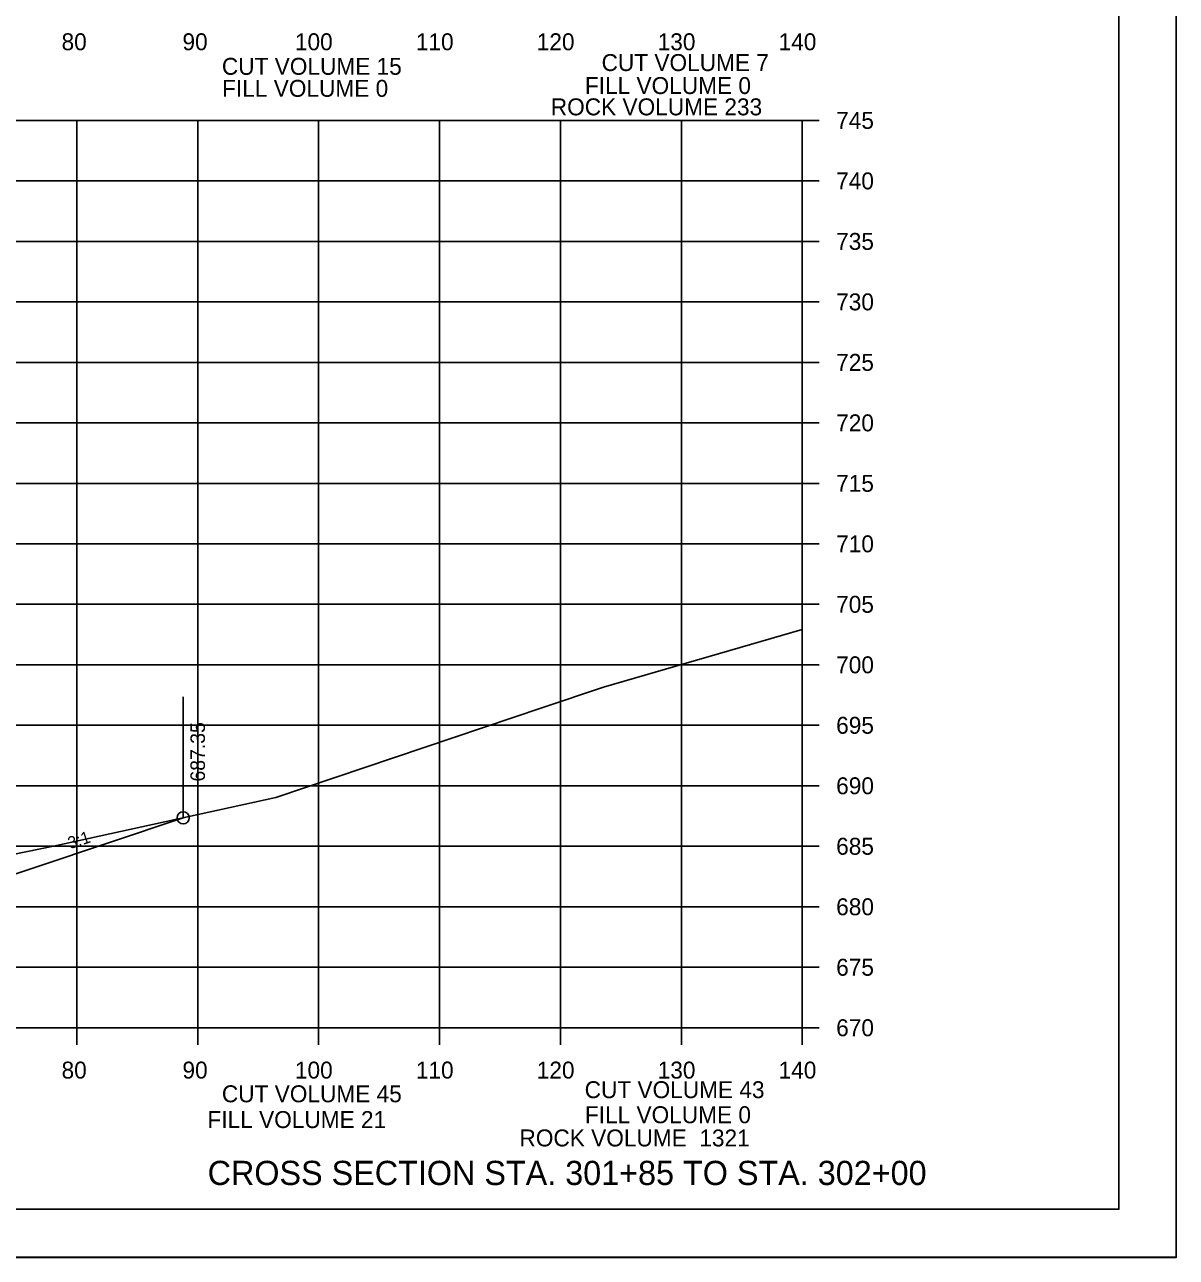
# Model space of a CAD drawing. Extents: x 1370515 to 1370849, y 383299 to 386073.
# Drawn here: x 1370753.5 to 1370848.7, y 383726.1 to 383828 of the extents above; entities that cross this region are included whole.
import ezdxf

# ---------------------------------------------------------------- set-up
doc = ezdxf.new("R2010")
doc.units = 0
for name, color, linetype in [('R_Axis', 7, 'Continuous'), ('R_Axis Annot', 7, 'Continuous'), ('R_Border', 7, 'Continuous'), ('R_Draft', 7, 'Continuous'), ('R_Exist Surface', 7, 'Continuous'), ('R_Fin Surface', 7, 'Continuous'), ('R_Grid', 7, 'Continuous'), ('R_No Plot', 7, 'Continuous'), ('R_Xsect Elev', 7, 'Continuous'), ('R_Xsect Slope', 7, 'Continuous')]:
    doc.layers.add(name, color=color, linetype=linetype)

msp = doc.modelspace()

# ---------------------------------------------------------------- linework, layer by layer
at = {"layer": 'R_Axis'}
for p, q in [((1370819.2, 383820.08), (1370816.4, 383820.08)), ((1370817.8, 383745.08), (1370817.8, 383820.08)), ((1370819.2, 383815.08), (1370816.4, 383815.08)), ((1370819.2, 383810.08), (1370816.4, 383810.08)), ((1370819.2, 383805.08), (1370816.4, 383805.08)), ((1370819.2, 383800.08), (1370816.4, 383800.08)), ((1370819.2, 383795.08), (1370816.4, 383795.08)), ((1370819.2, 383790.08), (1370816.4, 383790.08)), ((1370819.2, 383785.08), (1370816.4, 383785.08)), ((1370819.2, 383780.08), (1370816.4, 383780.08)), ((1370819.2, 383775.08), (1370816.4, 383775.08)), ((1370819.2, 383770.08), (1370816.4, 383770.08)), ((1370819.2, 383765.08), (1370816.4, 383765.08)), ((1370819.2, 383760.08), (1370816.4, 383760.08)), ((1370819.2, 383755.08), (1370816.4, 383755.08)), ((1370819.2, 383750.08), (1370816.4, 383750.08)), ((1370757.8, 383743.68), (1370757.8, 383746.48)), ((1370767.8, 383743.68), (1370767.8, 383746.48)), ((1370777.8, 383743.68), (1370777.8, 383746.48)), ((1370787.8, 383743.68), (1370787.8, 383746.48)), ((1370797.8, 383743.68), (1370797.8, 383746.48)), ((1370807.8, 383743.68), (1370807.8, 383746.48)), ((1370817.8, 383743.68), (1370817.8, 383746.48)), ((1370537.8, 383745.08), (1370817.8, 383745.08)), ((1370819.2, 383745.08), (1370816.4, 383745.08))]:
    msp.add_line(p, q, dxfattribs=at)
at = {"layer": 'R_Border'}
for q in [(1370843.98, 383935.54), (1370527.8, 383730.08)]:
    msp.add_line((1370843.98, 383730.08), q, dxfattribs=at)
at = {"layer": 'R_Exist Surface'}
msp.add_lwpolyline([(1370747.77, 383758.45), (1370755.87, 383760.09), (1370774.25, 383764.1), (1370796.33, 383771.54), (1370801.35, 383773.24), (1370817.8, 383778)], dxfattribs=at)
at = {"layer": 'R_Fin Surface'}
msp.add_lwpolyline([(1370637, 383775.29), (1370643.59, 383772.47), (1370651.8, 383775.21), (1370657.8, 383776.71), (1370665.8, 383776.86), (1370677.8, 383777.08), (1370689.8, 383776.84), (1370697.8, 383776.52), (1370703.09, 383775.19), (1370703.8, 383775.02), (1370741.22, 383756.3), (1370748.22, 383756.3), (1370766.6, 383762.43)], dxfattribs=at)
at = {"layer": 'R_Grid'}
for p, q in [((1370537.8, 383820.08), (1370817.8, 383820.08)), ((1370757.8, 383745.08), (1370757.8, 383820.08)), ((1370767.8, 383745.08), (1370767.8, 383820.08)), ((1370777.8, 383745.08), (1370777.8, 383820.08)), ((1370787.8, 383745.08), (1370787.8, 383820.08)), ((1370797.8, 383745.08), (1370797.8, 383820.08)), ((1370807.8, 383745.08), (1370807.8, 383820.08)), ((1370817.8, 383745.08), (1370817.8, 383820.08)), ((1370537.8, 383815.08), (1370817.8, 383815.08)), ((1370537.8, 383810.08), (1370817.8, 383810.08)), ((1370537.8, 383805.08), (1370817.8, 383805.08)), ((1370537.8, 383800.08), (1370817.8, 383800.08)), ((1370537.8, 383795.08), (1370817.8, 383795.08)), ((1370537.8, 383790.08), (1370817.8, 383790.08)), ((1370537.8, 383785.08), (1370817.8, 383785.08)), ((1370537.8, 383780.08), (1370817.8, 383780.08)), ((1370537.8, 383775.08), (1370817.8, 383775.08)), ((1370537.8, 383770.08), (1370817.8, 383770.08)), ((1370537.8, 383765.08), (1370817.8, 383765.08)), ((1370537.8, 383760.08), (1370817.8, 383760.08)), ((1370537.8, 383755.08), (1370817.8, 383755.08)), ((1370537.8, 383750.08), (1370817.8, 383750.08)), ((1370537.8, 383745.08), (1370817.8, 383745.08))]:
    msp.add_line(p, q, dxfattribs=at)
at = {"layer": 'R_No Plot'}
msp.add_line((1370515.4, 383726.11), (1370848.73, 383726.11), dxfattribs=at)
for points in [[(1370515.39, 383939.44), (1370848.73, 383939.44), (1370848.73, 383726.1), (1370515.39, 383726.1)], [(1370761.72, 383935.54), (1370761.72, 383925.66), (1370797.45, 383925.66), (1370797.45, 383922.74), (1370820.65, 383922.74), (1370820.65, 383899.53), (1370843.98, 383899.53), (1370843.98, 383730.08), (1370527.8, 383730.08), (1370527.8, 383935.54)]]:
    msp.add_lwpolyline(points, close=True, dxfattribs=at)
msp.add_circle((1370766.6, 383762.43), 0.5, dxfattribs=at)
at = {"layer": 'R_Xsect Elev'}
msp.add_line((1370766.6, 383762.43), (1370766.6, 383772.43), dxfattribs=at)

# ---------------------------------------------------------------- texts
at = {"layer": 'R_Axis Annot'}
for s, p in [('80', (1370756.54, 383825.88)), ('90', (1370766.54, 383825.88)), ('100', (1370775.84, 383825.88)), ('110', (1370785.84, 383825.88)), ('120', (1370795.84, 383825.88)), ('130', (1370805.84, 383825.88)), ('140', (1370815.84, 383825.88)), ('CUT VOLUME 15', (1370769.8, 383823.85)), ('CUT VOLUME 7', (1370801.2, 383824.16)), ('FILL VOLUME 0', (1370769.82, 383822.03)), ('FILL VOLUME 0', (1370799.82, 383822.26)), ('ROCK VOLUME 233', (1370797, 383820.5)), ('745', (1370820.6, 383819.38)), ('740', (1370820.6, 383814.38)), ('735', (1370820.6, 383809.38)), ('730', (1370820.6, 383804.38)), ('725', (1370820.6, 383799.38)), ('720', (1370820.6, 383794.38)), ('715', (1370820.6, 383789.38)), ('710', (1370820.6, 383784.38)), ('705', (1370820.6, 383779.38)), ('700', (1370820.6, 383774.38)), ('695', (1370820.6, 383769.38)), ('690', (1370820.6, 383764.38)), ('685', (1370820.6, 383759.38)), ('680', (1370820.6, 383754.38)), ('675', (1370820.6, 383749.38)), ('670', (1370820.6, 383744.38)), ('80', (1370756.54, 383740.88)), ('90', (1370766.54, 383740.88)), ('100', (1370775.84, 383740.88)), ('110', (1370785.84, 383740.88)), ('120', (1370795.84, 383740.88)), ('130', (1370805.84, 383740.88)), ('140', (1370815.84, 383740.88)), ('CUT VOLUME 43', (1370799.8, 383739.26)), ('CUT VOLUME 45', (1370769.8, 383738.92)), ('FILL VOLUME 0', (1370799.82, 383737.19)), ('FILL VOLUME 21', (1370768.61, 383736.79)), ('ROCK VOLUME  1321', (1370794.41, 383735.27))]:
    msp.add_text(s, height=1.4, dxfattribs=at).set_placement(p)
at = {"layer": 'R_Draft'}
msp.add_text('CROSS SECTION STA. 301+85 TO STA. 302+00', height=2, dxfattribs=at).set_placement((1370768.62, 383732.08))
at = {"layer": 'R_No Plot'}
for p in [(1370801.3, 383773.19), (1370774.21, 383764.05)]:
    msp.add_text('+', height=0.1, dxfattribs=at).set_placement(p)
at = {"layer": 'R_Xsect Elev'}
msp.add_text('687.35', height=1.2, rotation=90, dxfattribs=at).set_placement((1370768.4, 383765.43))
at = {"layer": 'R_Xsect Slope'}
msp.add_text('3:1', height=1, rotation=18.4349, dxfattribs=at).set_placement((1370757.25, 383759.84))

doc.saveas('drawing.dxf')
